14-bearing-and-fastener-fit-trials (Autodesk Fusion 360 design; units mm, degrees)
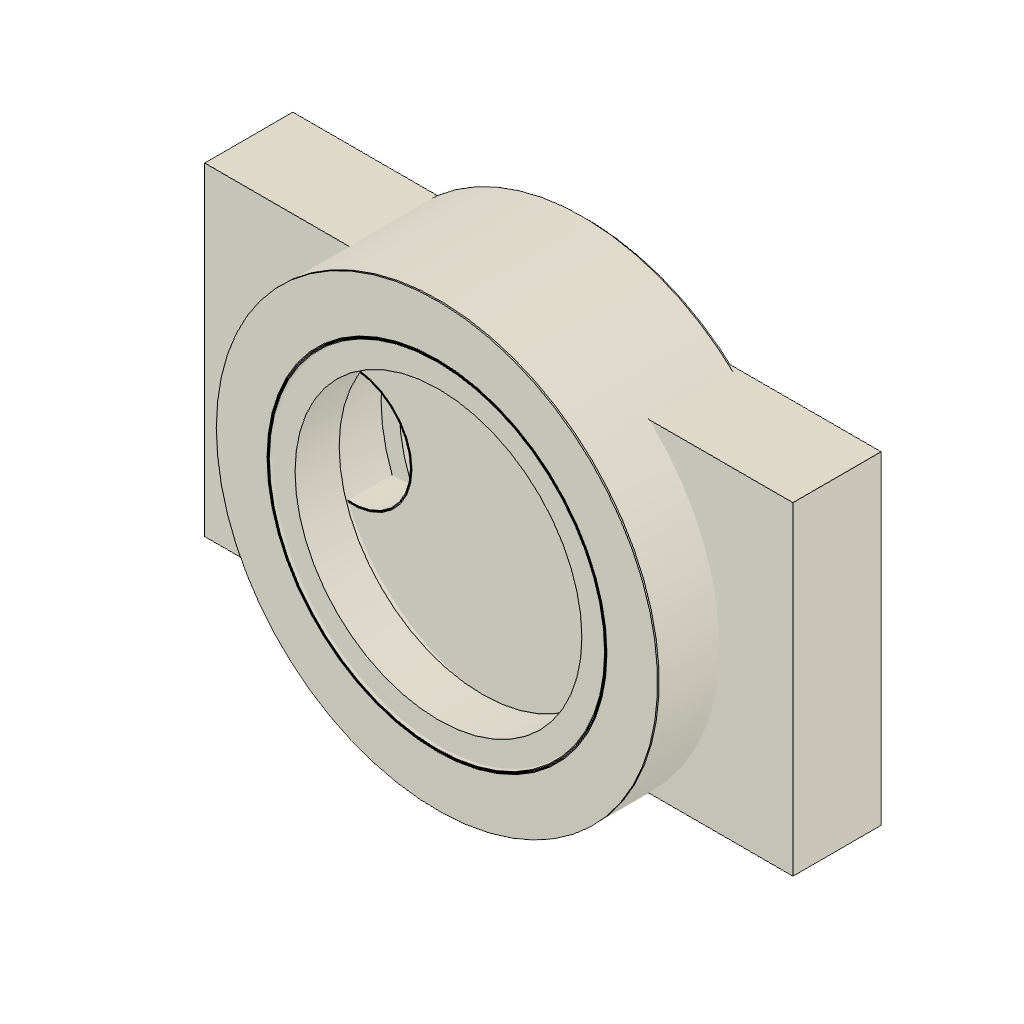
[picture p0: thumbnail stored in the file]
part number: 2026-11-02-20-20-23-688
part number: 2026-11-02-20-20-23-889
part number: 2026-11-02-20-20-23-959
part number: 2026-11-02-20-20-24-041
part number: 2026-11-02-20-20-24-142
part number: 2026-11-02-20-20-24-261
part number: 2026-11-02-20-20-24-400
part number: 2026-11-02-20-20-24-565
part number: 2026-11-02-20-20-24-753
part number: 2026-11-02-20-20-24-962
part number: 2026-11-02-20-20-25-426
part number: 2026-11-02-20-20-25-979
parameter "bearingDiameter" = 22 comment "Nominal 608 outside diameter."
parameter "entry" = 0.4 comment "Bearing mouth chamfer."
parameter "bed" = 0.3 comment "Bed edge relief."
parameter "nutAF" = 7.2 comment "Trial nut AF."
parameter "nutDepth" = 4 comment "Nut pocket depth."
work_plane "WorkPlane1" AlongDistance 0 ExtraOffset 0
work_plane "WorkPlane1" AlongDistance 0 ExtraOffset 0
sketch "Coupon Blank sketch" plane through (0, 0, 0) normal (0, 0, 1) x axis (1, 0, 0)
  circle C1 centre (0, 0) radius 15
  dimension "d10" diameter C1 = 30
extrude "Extrude1" new body sketch "Coupon Blank sketch" along normal blind 10.1
work_plane "WorkPlane2" AlongDistance 0 ExtraOffset 0
sketch "Seal Relief sketch" plane through (0, 0, 0) normal (0, 0, 1) x axis (1, 0, 0)
  circle C1 centre (0, 0) radius 9.75
  dimension "d15" diameter C1 = 19.5
extrude "Extrude2" cut sketch "Seal Relief sketch" along normal blind 10.1
work_plane "WorkPlane3" AlongDistance 0 ExtraOffset 0
sketch "Seat 22.0 sketch" plane through (0, 0, 0) normal (0, 0, 1) x axis (1, 0, 0)
  circle C1 centre (0, 0) radius 11
  dimension "d20" diameter C1 = 22
extrude "Extrude3" cut sketch "Seat 22.0 sketch" along normal blind 7.1
chamfer "Chamfer1" distance 0.4 (= "entry")
chamfer "Chamfer2" distance 0.3 (= "bed")
work_plane "WorkPlane1" AlongDistance 0 ExtraOffset 0
sketch "Coupon Blank sketch" plane through (0, 0, 0) normal (0, 0, 1) x axis (1, 0, 0)
  circle C1 centre (0, 0) radius 15
  dimension "d27" diameter C1 = 30
extrude "Extrude1" new body sketch "Coupon Blank sketch" along normal blind 10.1
work_plane "WorkPlane2" AlongDistance 0 ExtraOffset 0
sketch "Seal Relief sketch" plane through (0, 0, 0) normal (0, 0, 1) x axis (1, 0, 0)
  circle C1 centre (0, 0) radius 9.75
  dimension "d32" diameter C1 = 19.5
extrude "Extrude2" cut sketch "Seal Relief sketch" along normal blind 10.1
work_plane "WorkPlane3" AlongDistance 0 ExtraOffset 0
sketch "Seat 22.1 sketch" plane through (0, 0, 0) normal (0, 0, 1) x axis (1, 0, 0)
  circle C1 centre (0, 0) radius 11.05
  dimension "d37" diameter C1 = 22.1
extrude "Extrude3" cut sketch "Seat 22.1 sketch" along normal blind 7.1
chamfer "Chamfer1" distance 0.4 (= "entry")
chamfer "Chamfer2" distance 0.3 (= "bed")
work_plane "WorkPlane1" AlongDistance 0 ExtraOffset 0
sketch "Coupon Blank sketch" plane through (0, 0, 0) normal (0, 0, 1) x axis (1, 0, 0)
  circle C1 centre (0, 0) radius 15
  dimension "d44" diameter C1 = 30
extrude "Extrude1" new body sketch "Coupon Blank sketch" along normal blind 10.1
work_plane "WorkPlane2" AlongDistance 0 ExtraOffset 0
sketch "Seal Relief sketch" plane through (0, 0, 0) normal (0, 0, 1) x axis (1, 0, 0)
  circle C1 centre (0, 0) radius 9.75
  dimension "d49" diameter C1 = 19.5
extrude "Extrude2" cut sketch "Seal Relief sketch" along normal blind 10.1
work_plane "WorkPlane3" AlongDistance 0 ExtraOffset 0
sketch "Seat 22.2 sketch" plane through (0, 0, 0) normal (0, 0, 1) x axis (1, 0, 0)
  circle C1 centre (0, 0) radius 11.1
  dimension "d54" diameter C1 = 22.2
extrude "Extrude3" cut sketch "Seat 22.2 sketch" along normal blind 7.1
chamfer "Chamfer1" distance 0.4 (= "entry")
chamfer "Chamfer2" distance 0.3 (= "bed")
work_plane "WorkPlane1" AlongDistance 0 ExtraOffset 0
sketch "Coupon Blank sketch" plane through (0, 0, 0) normal (0, 0, 1) x axis (1, 0, 0)
  circle C1 centre (0, 0) radius 15
  dimension "d61" diameter C1 = 30
extrude "Extrude1" new body sketch "Coupon Blank sketch" along normal blind 10.1
work_plane "WorkPlane2" AlongDistance 0 ExtraOffset 0
sketch "Seal Relief sketch" plane through (0, 0, 0) normal (0, 0, 1) x axis (1, 0, 0)
  circle C1 centre (0, 0) radius 9.75
  dimension "d66" diameter C1 = 19.5
extrude "Extrude2" cut sketch "Seal Relief sketch" along normal blind 10.1
work_plane "WorkPlane3" AlongDistance 0 ExtraOffset 0
sketch "Seat 22.3 sketch" plane through (0, 0, 0) normal (0, 0, 1) x axis (1, 0, 0)
  circle C1 centre (0, 0) radius 11.15
  dimension "d71" diameter C1 = 22.3
extrude "Extrude3" cut sketch "Seat 22.3 sketch" along normal blind 7.1
chamfer "Chamfer1" distance 0.4 (= "entry")
chamfer "Chamfer2" distance 0.3 (= "bed")
work_plane "WorkPlane1" AlongDistance 0 ExtraOffset 0
sketch "Coupon Blank sketch" plane through (0, 0, 0) normal (0, 0, 1) x axis (1, 0, 0)
  circle C1 centre (0, 0) radius 15
  dimension "d78" diameter C1 = 30
extrude "Extrude1" new body sketch "Coupon Blank sketch" along normal blind 10.2
work_plane "WorkPlane2" AlongDistance 0 ExtraOffset 0
sketch "Seal Relief sketch" plane through (0, 0, 0) normal (0, 0, 1) x axis (1, 0, 0)
  circle C1 centre (0, 0) radius 9.75
  dimension "d83" diameter C1 = 19.5
extrude "Extrude2" cut sketch "Seal Relief sketch" along normal blind 10.2
work_plane "WorkPlane3" AlongDistance 3 ExtraOffset 0
sketch "Seat 22.0 sketch" plane through (0, 0, 3) normal (0, 0, 1) x axis (1, 0, 0)
  circle C1 centre (0, 0) radius 11
  dimension "d88" diameter C1 = 22
extrude "Extrude3" cut sketch "Seat 22.0 sketch" along normal blind 7.2
chamfer "Chamfer1" distance 0.4 (= "entry")
chamfer "Chamfer2" distance 0.3 (= "bed")
work_plane "WorkPlane1" AlongDistance 0 ExtraOffset 0
sketch "Coupon Blank sketch" plane through (0, 0, 0) normal (0, 0, 1) x axis (1, 0, 0)
  circle C1 centre (0, 0) radius 15
  dimension "d95" diameter C1 = 30
extrude "Extrude1" new body sketch "Coupon Blank sketch" along normal blind 10.2
work_plane "WorkPlane2" AlongDistance 0 ExtraOffset 0
sketch "Seal Relief sketch" plane through (0, 0, 0) normal (0, 0, 1) x axis (1, 0, 0)
  circle C1 centre (0, 0) radius 9.75
  dimension "d100" diameter C1 = 19.5
extrude "Extrude2" cut sketch "Seal Relief sketch" along normal blind 10.2
work_plane "WorkPlane3" AlongDistance 3 ExtraOffset 0
sketch "Seat 22.1 sketch" plane through (0, 0, 3) normal (0, 0, 1) x axis (1, 0, 0)
  circle C1 centre (0, 0) radius 11.05
  dimension "d105" diameter C1 = 22.1
extrude "Extrude3" cut sketch "Seat 22.1 sketch" along normal blind 7.2
chamfer "Chamfer1" distance 0.4 (= "entry")
chamfer "Chamfer2" distance 0.3 (= "bed")
work_plane "WorkPlane1" AlongDistance 0 ExtraOffset 0
sketch "Coupon Blank sketch" plane through (0, 0, 0) normal (0, 0, 1) x axis (1, 0, 0)
  circle C1 centre (0, 0) radius 15
  dimension "d112" diameter C1 = 30
extrude "Extrude1" new body sketch "Coupon Blank sketch" along normal blind 10.2
work_plane "WorkPlane2" AlongDistance 0 ExtraOffset 0
sketch "Seal Relief sketch" plane through (0, 0, 0) normal (0, 0, 1) x axis (1, 0, 0)
  circle C1 centre (0, 0) radius 9.75
  dimension "d117" diameter C1 = 19.5
extrude "Extrude2" cut sketch "Seal Relief sketch" along normal blind 10.2
work_plane "WorkPlane3" AlongDistance 3 ExtraOffset 0
sketch "Seat 22.2 sketch" plane through (0, 0, 3) normal (0, 0, 1) x axis (1, 0, 0)
  circle C1 centre (0, 0) radius 11.1
  dimension "d122" diameter C1 = 22.2
extrude "Extrude3" cut sketch "Seat 22.2 sketch" along normal blind 7.2
chamfer "Chamfer1" distance 0.4 (= "entry")
chamfer "Chamfer2" distance 0.3 (= "bed")
work_plane "WorkPlane1" AlongDistance 0 ExtraOffset 0
sketch "Coupon Blank sketch" plane through (0, 0, 0) normal (0, 0, 1) x axis (1, 0, 0)
  circle C1 centre (0, 0) radius 15
  dimension "d129" diameter C1 = 30
extrude "Extrude1" new body sketch "Coupon Blank sketch" along normal blind 10.2
work_plane "WorkPlane2" AlongDistance 0 ExtraOffset 0
sketch "Seal Relief sketch" plane through (0, 0, 0) normal (0, 0, 1) x axis (1, 0, 0)
  circle C1 centre (0, 0) radius 9.75
  dimension "d134" diameter C1 = 19.5
extrude "Extrude2" cut sketch "Seal Relief sketch" along normal blind 10.2
work_plane "WorkPlane3" AlongDistance 3 ExtraOffset 0
sketch "Seat 22.3 sketch" plane through (0, 0, 3) normal (0, 0, 1) x axis (1, 0, 0)
  circle C1 centre (0, 0) radius 11.15
  dimension "d139" diameter C1 = 22.3
extrude "Extrude3" cut sketch "Seat 22.3 sketch" along normal blind 7.2
chamfer "Chamfer1" distance 0.4 (= "entry")
chamfer "Chamfer2" distance 0.3 (= "bed")
sketch "Trial Block" plane through (0, 0, 0) normal (0, 0, 1) x axis (1, 0, 0)
  line L1 (20, -11) -> (-20, -11)
  line L2 (20, 11) -> (20, -11)
  line L3 (-20, 11) -> (20, 11)
  line L4 (-20, -11) -> (-20, 11)
  line L5 (20, 11) -> (-20, -11)
  point P1 (0, 0)
  point P2 (-20, -11)
  point P3 (20, -11)
  point P4 (20, 11)
  horizontal L1
  vertical L2
  horizontal L3
  vertical L4
  midpoint P1 L5
  dimension "d144" distance P2 P3 = 40
  dimension "d145" distance P3 P4 = 22
extrude "Extrude1" new body sketch "Trial Block" profile of L1 L2 L3 L4 along normal blind 6
sketch "Sleeve Trial" plane through (0, 0, 0) normal (0, 0, 1) x axis (1, 0, 0)
  line L1 (-10, 0) -> (0, 0)
  circle C1 centre (-10, 0) radius 4
  point P1 (0, 0)
  point P2 (-10, 0)
  horizontal L1
  dimension "d148" distance P1 P2 = 10 (= "abs(-10 mm)")
  dimension "d149" diameter C1 = 8
extrude "Extrude2" cut sketch "Sleeve Trial" profile of C1 along normal blind 6
sketch "Bolt Clearance" plane through (0, 0, 0) normal (0, 0, 1) x axis (1, 0, 0)
  line L1 (10, 0) -> (0, 0)
  circle C1 centre (10, 0) radius 2.15
  point P1 (0, 0)
  point P2 (10, 0)
  horizontal L1
  dimension "d152" distance P1 P2 = 10 (= "abs(10 mm)")
  dimension "d153" diameter C1 = 4.3
extrude "Extrude3" cut sketch "Bolt Clearance" profile of C1 along normal blind 6
sketch "Nut Trial" plane through (0, 0, 0) normal (0, 0, 1) x axis (1, 0, 0)
  line L1 (10, 0) -> (0, 0)
  line L2 (12.0207, 3.5) -> (14.0415, 0)
  line L3 (7.9793, 3.5) -> (12.0207, 3.5)
  line L4 (5.9585, 0) -> (7.9793, 3.5)
  line L5 (7.9793, -3.5) -> (5.9585, 0)
  line L6 (12.0207, -3.5) -> (7.9793, -3.5)
  line L7 (14.0415, 0) -> (12.0207, -3.5)
  circle C1 centre (10, 0) radius 4.0415
  point P3 (14.0415, 0)
  point P4 (12.0207, 3.5)
  point P5 (7.9793, 3.5)
  point P6 (5.9585, 0)
  point P7 (7.9793, -3.5)
  point P8 (12.0207, -3.5)
  point P1 (0, 0)
  point P2 (10, 0)
  horizontal L1
  coincident C1 P3
  coincident C1 P4
  coincident C1 P5
  coincident C1 P6
  coincident C1 P7
  coincident C1 P8
  equal L2 L3
  equal L2 L4
  equal L2 L5
  equal L2 L6
  equal L2 L7
  horizontal L3
  dimension "d156" distance P1 P2 = 10 (= "abs(10 mm)")
  dimension "d157" diameter C1 = 8.0829 (= "2 * ( 7.0 mm ) / sqrt(3)")
extrude "Extrude4" cut sketch "Nut Trial" profile of L2 L3 L4 L5 L6 L7 along normal blind 4 (= "nutDepth")
sketch "Trial Block" plane through (0, 0, 0) normal (0, 0, 1) x axis (1, 0, 0)
  line L1 (20, -11) -> (-20, -11)
  line L2 (20, 11) -> (20, -11)
  line L3 (-20, 11) -> (20, 11)
  line L4 (-20, -11) -> (-20, 11)
  line L5 (20, 11) -> (-20, -11)
  point P1 (0, 0)
  point P2 (-20, -11)
  point P3 (20, -11)
  point P4 (20, 11)
  horizontal L1
  vertical L2
  horizontal L3
  vertical L4
  midpoint P1 L5
  dimension "d160" distance P2 P3 = 40
  dimension "d161" distance P3 P4 = 22
extrude "Extrude1" new body sketch "Trial Block" profile of L1 L2 L3 L4 along normal blind 6
sketch "Sleeve Trial" plane through (0, 0, 0) normal (0, 0, 1) x axis (1, 0, 0)
  line L1 (-10, 0) -> (0, 0)
  circle C1 centre (-10, 0) radius 4.05
  point P1 (0, 0)
  point P2 (-10, 0)
  horizontal L1
  dimension "d164" distance P1 P2 = 10 (= "abs(-10 mm)")
  dimension "d165" diameter C1 = 8.1
extrude "Extrude2" cut sketch "Sleeve Trial" profile of C1 along normal blind 6
sketch "Bolt Clearance" plane through (0, 0, 0) normal (0, 0, 1) x axis (1, 0, 0)
  line L1 (10, 0) -> (0, 0)
  circle C1 centre (10, 0) radius 2.15
  point P1 (0, 0)
  point P2 (10, 0)
  horizontal L1
  dimension "d168" distance P1 P2 = 10 (= "abs(10 mm)")
  dimension "d169" diameter C1 = 4.3
extrude "Extrude3" cut sketch "Bolt Clearance" profile of C1 along normal blind 6
sketch "Nut Trial" plane through (0, 0, 0) normal (0, 0, 1) x axis (1, 0, 0)
  line L1 (10, 0) -> (0, 0)
  line L2 (12.0496, 3.55) -> (14.0992, 0)
  line L3 (7.9504, 3.55) -> (12.0496, 3.55)
  line L4 (5.9008, 0) -> (7.9504, 3.55)
  line L5 (7.9504, -3.55) -> (5.9008, 0)
  line L6 (12.0496, -3.55) -> (7.9504, -3.55)
  line L7 (14.0992, 0) -> (12.0496, -3.55)
  circle C1 centre (10, 0) radius 4.0992
  point P3 (14.0992, 0)
  point P4 (12.0496, 3.55)
  point P5 (7.9504, 3.55)
  point P6 (5.9008, 0)
  point P7 (7.9504, -3.55)
  point P8 (12.0496, -3.55)
  point P1 (0, 0)
  point P2 (10, 0)
  horizontal L1
  coincident C1 P3
  coincident C1 P4
  coincident C1 P5
  coincident C1 P6
  coincident C1 P7
  coincident C1 P8
  equal L2 L3
  equal L2 L4
  equal L2 L5
  equal L2 L6
  equal L2 L7
  horizontal L3
  dimension "d172" distance P1 P2 = 10 (= "abs(10 mm)")
  dimension "d173" diameter C1 = 8.1984 (= "2 * ( 7.1 mm ) / sqrt(3)")
extrude "Extrude4" cut sketch "Nut Trial" profile of L2 L3 L4 L5 L6 L7 along normal blind 4 (= "nutDepth")
sketch "Trial Block" plane through (0, 0, 0) normal (0, 0, 1) x axis (1, 0, 0)
  line L1 (20, -11) -> (-20, -11)
  line L2 (20, 11) -> (20, -11)
  line L3 (-20, 11) -> (20, 11)
  line L4 (-20, -11) -> (-20, 11)
  line L5 (20, 11) -> (-20, -11)
  point P1 (0, 0)
  point P2 (-20, -11)
  point P3 (20, -11)
  point P4 (20, 11)
  horizontal L1
  vertical L2
  horizontal L3
  vertical L4
  midpoint P1 L5
  dimension "d176" distance P2 P3 = 40
  dimension "d177" distance P3 P4 = 22
extrude "Extrude1" new body sketch "Trial Block" profile of L1 L2 L3 L4 along normal blind 6
sketch "Sleeve Trial" plane through (0, 0, 0) normal (0, 0, 1) x axis (1, 0, 0)
  line L1 (-10, 0) -> (0, 0)
  circle C1 centre (-10, 0) radius 4.1
  point P1 (0, 0)
  point P2 (-10, 0)
  horizontal L1
  dimension "d180" distance P1 P2 = 10 (= "abs(-10 mm)")
  dimension "d181" diameter C1 = 8.2
extrude "Extrude2" cut sketch "Sleeve Trial" profile of C1 along normal blind 6
sketch "Bolt Clearance" plane through (0, 0, 0) normal (0, 0, 1) x axis (1, 0, 0)
  line L1 (10, 0) -> (0, 0)
  circle C1 centre (10, 0) radius 2.15
  point P1 (0, 0)
  point P2 (10, 0)
  horizontal L1
  dimension "d184" distance P1 P2 = 10 (= "abs(10 mm)")
  dimension "d185" diameter C1 = 4.3
extrude "Extrude3" cut sketch "Bolt Clearance" profile of C1 along normal blind 6
sketch "Nut Trial" plane through (0, 0, 0) normal (0, 0, 1) x axis (1, 0, 0)
  line L1 (10, 0) -> (0, 0)
  line L2 (12.0785, 3.6) -> (14.1569, 0)
  line L3 (7.9215, 3.6) -> (12.0785, 3.6)
  line L4 (5.8431, 0) -> (7.9215, 3.6)
  line L5 (7.9215, -3.6) -> (5.8431, 0)
  line L6 (12.0785, -3.6) -> (7.9215, -3.6)
  line L7 (14.1569, 0) -> (12.0785, -3.6)
  circle C1 centre (10, 0) radius 4.1569
  point P3 (14.1569, 0)
  point P4 (12.0785, 3.6)
  point P5 (7.9215, 3.6)
  point P6 (5.8431, 0)
  point P7 (7.9215, -3.6)
  point P8 (12.0785, -3.6)
  point P1 (0, 0)
  point P2 (10, 0)
  horizontal L1
  coincident C1 P3
  coincident C1 P4
  coincident C1 P5
  coincident C1 P6
  coincident C1 P7
  coincident C1 P8
  equal L2 L3
  equal L2 L4
  equal L2 L5
  equal L2 L6
  equal L2 L7
  horizontal L3
  dimension "d188" distance P1 P2 = 10 (= "abs(10 mm)")
  dimension "d189" diameter C1 = 8.3138 (= "2 * ( 7.2 mm ) / sqrt(3)")
extrude "Extrude4" cut sketch "Nut Trial" profile of L2 L3 L4 L5 L6 L7 along normal blind 4 (= "nutDepth")
chamfer "Chamfer1" distance 0.3 (= "bed")
chamfer "Chamfer2" sketch "Coupon Blank sketch" + "Seal Relief sketch" distance 0.3 (= "bed")
chamfer "Chamfer1" distance 0.3 (= "bed")
chamfer "Chamfer2" sketch "Coupon Blank sketch" + "Seal Relief sketch" distance 0.3 (= "bed")
chamfer "Chamfer1" distance 0.3 (= "bed")
chamfer "Chamfer2" sketch "Coupon Blank sketch" + "Seal Relief sketch" distance 0.3 (= "bed")
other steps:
create_component "CreateComponent1"
create_component "CreateComponent2"
create_component "CreateComponent3"
create_component "CreateComponent4"
create_component "CreateComponent5"
create_component "CreateComponent6"
create_component "CreateComponent7"
create_component "CreateComponent8"
create_component "CreateComponent9"
create_component "CreateComponent10"
create_component "CreateComponent11"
